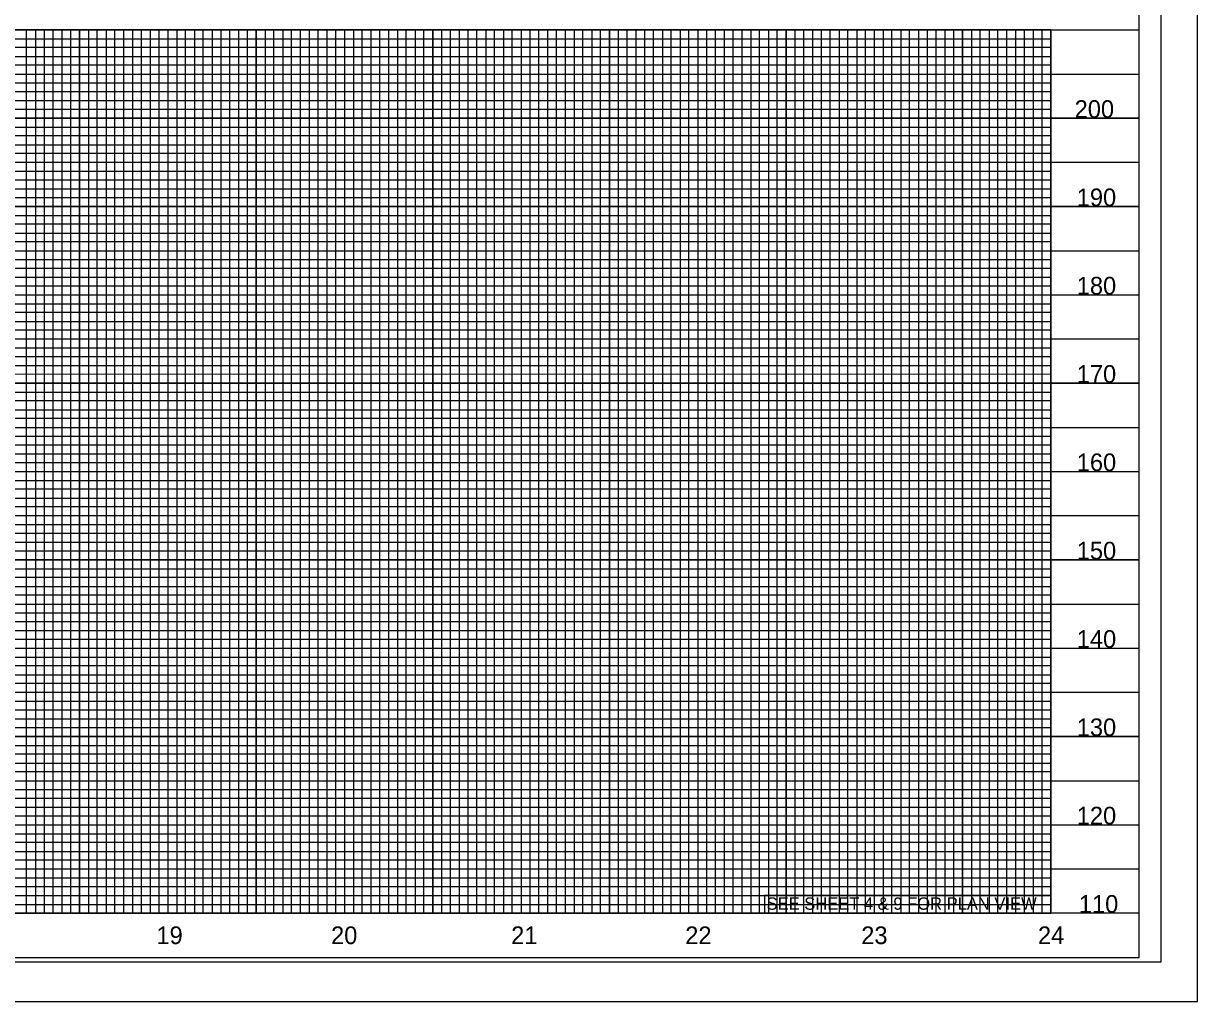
# Model space of a CAD drawing. Extents: x 1779926 to 1781626, y 618464 to 619564.
# Drawn here: x 1780961 to 1781626, y 618464 to 619018 of the extents above; entities that cross this region are included whole.
import ezdxf

# ---------------------------------------------------------------- set-up
doc = ezdxf.new("R2010")
doc.units = 0
for name, color, linetype in [('Exist Vertical Profile Horizontal Axis Label Major', 7, 'Continuous'), ('Exist Vertical Profile Vertical Axis Label', 7, 'Continuous'), ('Prop DSN Text', 7, 'Continuous'), ('Prop Grid Mask', 7, 'Continuous'), ('Sheet DOT Grid CELL', 7, 'Continuous'), ('Sheet Layout Profile Border Port 2', 7, 'Continuous'), ('Sheet Plot Border Inside CELL', 7, 'Continuous'), ('Sheet Plot Border Outside CELL', 7, 'Continuous'), ('Sheet Profile CELL', 7, 'Continuous'), ('Sheet Profile Grid Major CELL', 7, 'Continuous'), ('Sheet Profile Grid Middle CELL', 7, 'Continuous'), ('Sheet Profile Grid Minor CELL', 7, 'Continuous')]:
    doc.layers.add(name, color=color, linetype=linetype)

msp = doc.modelspace()

# ---------------------------------------------------------------- linework, layer by layer
at = {"layer": 'Prop Grid Mask'}
msp.add_lwpolyline([(1781542.96, 618524.19), (1781380.71, 618524.19), (1781380.71, 618514.19), (1781542.96, 618514.19)], close=True, dxfattribs=at)
at = {"layer": 'Sheet DOT Grid CELL'}
for p, q in [((1780092.96, 619014.19), (1781592.85, 619014.19)), ((1780992.96, 619014.19), (1780992.96, 618514.19)), ((1781042.96, 619014.19), (1781042.96, 618514.19)), ((1781092.96, 619014.19), (1781092.96, 618514.19)), ((1781142.96, 619014.19), (1781142.96, 618514.19)), ((1781192.96, 619014.19), (1781192.96, 618514.19)), ((1781242.96, 619014.19), (1781242.96, 618514.19)), ((1781292.96, 619014.19), (1781292.96, 618514.19)), ((1781342.96, 619014.19), (1781342.96, 618514.19)), ((1781392.96, 619014.19), (1781392.96, 618514.19)), ((1781442.96, 619014.19), (1781442.96, 618514.19)), ((1781492.96, 619014.19), (1781492.96, 618514.19)), ((1781542.96, 619014.19), (1781542.96, 618514.19)), ((1780092.96, 618964.19), (1781592.85, 618964.19)), ((1780092.96, 618914.19), (1781592.85, 618914.19)), ((1780092.96, 618864.19), (1781592.85, 618864.19)), ((1780092.96, 618814.19), (1781592.85, 618814.19)), ((1780092.96, 618764.19), (1781592.85, 618764.19)), ((1780092.96, 618714.19), (1781592.85, 618714.19)), ((1780092.96, 618664.19), (1781592.85, 618664.19)), ((1780092.96, 618614.19), (1781592.85, 618614.19)), ((1780092.96, 618564.19), (1781592.85, 618564.19))]:
    msp.add_line(p, q, dxfattribs=at)
at = {"layer": 'Sheet Layout Profile Border Port 2'}
msp.add_line((1781542.96, 619014.19), (1781442.96, 619014.19), dxfattribs=at)
msp.add_lwpolyline([(1780142.96, 619014.19), (1781542.96, 619014.19), (1781542.96, 618514.19), (1780142.96, 618514.19)], close=True, dxfattribs=at)
msp.add_lwpolyline([(1781442.96, 619014.19), (1780142.96, 619014.19), (1780142.96, 618514.19), (1781542.96, 618514.19), (1781542.96, 619014.19)], dxfattribs=at)
at = {"layer": 'Sheet Plot Border Inside CELL'}
msp.add_lwpolyline([(1779938.96, 618486.64), (1781605.46, 618486.64), (1781605.46, 619541.74), (1779938.96, 619541.74)], close=True, dxfattribs=at)
at = {"layer": 'Sheet Plot Border Outside CELL'}
msp.add_lwpolyline([(1779925.96, 618464.19), (1781625.96, 618464.19), (1781625.96, 619564.19), (1779925.96, 619564.19)], close=True, dxfattribs=at)
at = {"layer": 'Sheet Profile CELL'}
for p, q in [((1780092.96, 619014.19), (1781592.96, 619014.19)), ((1781592.96, 618514.19), (1780092.96, 618514.19)), ((1780092.96, 618489.19), (1781592.96, 618489.19))]:
    msp.add_line(p, q, dxfattribs=at)
msp.add_lwpolyline([(1781592.96, 619539.19), (1780092.96, 619539.19), (1780092.96, 618489.19), (1781592.96, 618489.19)], close=True, dxfattribs=at)
at = {"layer": 'Sheet Profile Grid Major CELL'}
for p, q in [((1780992.96, 619014.19), (1781042.96, 619014.19)), ((1781092.96, 619014.19), (1781142.96, 619014.19)), ((1781192.96, 619014.19), (1781242.96, 619014.19)), ((1781292.96, 619014.19), (1781342.96, 619014.19)), ((1781392.96, 619014.19), (1781442.96, 619014.19)), ((1781492.96, 619014.19), (1781542.96, 619014.19)), ((1781492.96, 618514.19), (1781492.96, 618514.19))]:
    msp.add_line(p, q, dxfattribs=at)
for points in [[(1780942.96, 618514.19), (1780992.96, 618514.19), (1780992.96, 619014.19), (1781042.96, 619014.19), (1781042.96, 618514.19), (1781092.96, 618514.19), (1781092.96, 619014.19), (1781142.96, 619014.19), (1781142.96, 618514.19), (1781192.96, 618514.19), (1781192.96, 619014.19), (1781242.96, 619014.19), (1781242.96, 618514.19), (1781292.96, 618514.19), (1781292.96, 619014.19), (1781342.96, 619014.19), (1781342.96, 618514.19), (1781392.96, 618514.19), (1781392.96, 619014.19), (1781442.96, 619014.19), (1781442.96, 618514.19), (1781492.96, 618514.19), (1781492.96, 618514.19), (1781492.96, 619014.19), (1781542.96, 619014.19), (1781542.96, 618514.19)], [(1781592.96, 618964.19), (1780092.96, 618964.19)], [(1781592.96, 618914.19), (1780092.96, 618914.19), (1780092.96, 618864.19), (1781592.96, 618864.19)], [(1781592.96, 618814.19), (1780092.96, 618814.19), (1780092.96, 618764.19), (1781592.96, 618764.19)], [(1781592.96, 618714.19), (1780092.96, 618714.19), (1780092.96, 618664.19), (1781592.96, 618664.19)], [(1781592.96, 618614.19), (1780092.96, 618614.19), (1780092.96, 618614.19), (1780092.96, 618564.19), (1781592.96, 618564.19)], [(1781592.96, 618514.19), (1780092.96, 618514.19)]]:
    msp.add_lwpolyline(points, dxfattribs=at)
at = {"layer": 'Sheet Profile Grid Middle CELL'}
for points in [[(1780917.96, 619014.19), (1780967.96, 619014.19), (1780967.96, 618514.19), (1781017.96, 618514.19), (1781017.96, 619014.19), (1781067.96, 619014.19), (1781067.96, 618514.19), (1781117.96, 618514.19), (1781117.96, 619014.19), (1781167.96, 619014.19), (1781167.96, 618514.19), (1781217.96, 618514.19), (1781217.96, 619014.19), (1781267.96, 619014.19), (1781267.96, 618514.19), (1781317.96, 618514.19), (1781317.96, 619014.19), (1781367.96, 619014.19), (1781367.96, 618514.19), (1781417.96, 618514.19), (1781417.96, 619014.19), (1781467.96, 619014.19), (1781467.96, 618514.19), (1781517.96, 618514.19), (1781517.96, 619014.19)], [(1780092.96, 618989.19), (1781592.96, 618989.19)], [(1781592.96, 618939.19), (1780092.96, 618939.19), (1780092.96, 618889.19), (1781592.96, 618889.19)], [(1781592.96, 618839.19), (1780092.96, 618839.19), (1780092.96, 618789.19), (1781592.96, 618789.19)], [(1781592.96, 618739.19), (1780092.96, 618739.19), (1780092.96, 618689.19), (1781592.96, 618689.19)], [(1781592.96, 618639.19), (1780092.96, 618639.19), (1780092.96, 618589.19), (1781592.96, 618589.19)], [(1781592.96, 618539.19), (1780092.96, 618539.19)]]:
    msp.add_lwpolyline(points, dxfattribs=at)
at = {"layer": 'Sheet Profile Grid Minor CELL'}
for p, q in [((1780142.96, 619009.19), (1781542.96, 619009.19)), ((1781542.96, 619004.19), (1780142.96, 619004.19)), ((1780142.96, 618999.19), (1781542.96, 618999.19)), ((1781542.96, 618994.19), (1780142.96, 618994.19)), ((1780142.96, 618984.19), (1781542.96, 618984.19)), ((1781542.96, 618979.19), (1780142.96, 618979.19)), ((1780142.96, 618974.19), (1781542.96, 618974.19)), ((1781542.96, 618969.19), (1780142.96, 618969.19)), ((1780142.96, 618959.19), (1781542.96, 618959.19)), ((1781542.96, 618954.19), (1780142.96, 618954.19)), ((1780142.96, 618949.19), (1781542.96, 618949.19)), ((1781542.96, 618944.19), (1780142.96, 618944.19)), ((1780142.96, 618934.19), (1781542.96, 618934.19)), ((1781542.96, 618929.19), (1780142.96, 618929.19)), ((1780142.96, 618924.19), (1781542.96, 618924.19)), ((1781542.96, 618919.19), (1780142.96, 618919.19)), ((1780142.96, 618909.19), (1781542.96, 618909.19)), ((1781542.96, 618904.19), (1780142.96, 618904.19)), ((1780142.96, 618899.19), (1781542.96, 618899.19)), ((1781542.96, 618894.19), (1780142.96, 618894.19)), ((1780142.96, 618884.19), (1781542.96, 618884.19)), ((1781542.96, 618879.19), (1780142.96, 618879.19)), ((1780142.96, 618874.19), (1781542.96, 618874.19)), ((1781542.96, 618869.19), (1780142.96, 618869.19)), ((1780142.96, 618859.19), (1781542.96, 618859.19)), ((1781542.96, 618854.19), (1780142.96, 618854.19)), ((1780142.96, 618849.19), (1781542.96, 618849.19)), ((1781542.96, 618844.19), (1780142.96, 618844.19)), ((1780142.96, 618834.19), (1781542.96, 618834.19)), ((1781542.96, 618829.19), (1780142.96, 618829.19)), ((1780142.96, 618824.19), (1781542.96, 618824.19)), ((1781542.96, 618819.19), (1780142.96, 618819.34)), ((1780142.96, 618809.19), (1781542.96, 618809.19)), ((1781542.96, 618804.19), (1780142.96, 618804.19)), ((1780142.96, 618799.19), (1781542.96, 618799.19)), ((1781542.96, 618794.19), (1780142.96, 618794.19)), ((1780142.96, 618784.19), (1781542.96, 618784.19)), ((1781542.96, 618779.19), (1780142.96, 618779.19)), ((1780142.96, 618774.19), (1781542.96, 618774.19)), ((1781542.96, 618769.19), (1780142.96, 618769.19)), ((1780142.96, 618759.19), (1781542.96, 618759.19)), ((1781542.96, 618754.19), (1780142.96, 618754.19)), ((1780142.96, 618749.19), (1781542.96, 618749.19)), ((1781542.96, 618744.19), (1780142.96, 618744.19)), ((1780142.96, 618734.19), (1781542.96, 618734.19)), ((1781542.96, 618729.19), (1780142.96, 618729.19)), ((1780142.96, 618724.19), (1781542.96, 618724.19)), ((1781542.96, 618719.19), (1780142.96, 618719.19)), ((1780142.96, 618709.19), (1781542.96, 618709.19)), ((1781542.96, 618704.19), (1780142.96, 618704.19)), ((1780142.96, 618699.19), (1781542.96, 618699.19)), ((1781542.96, 618694.19), (1780142.96, 618694.19)), ((1780142.96, 618684.19), (1781542.96, 618684.19)), ((1781542.96, 618679.19), (1780142.96, 618679.19)), ((1780142.96, 618674.19), (1781542.96, 618674.19)), ((1781542.96, 618669.19), (1780142.96, 618669.19)), ((1780142.96, 618659.19), (1781542.96, 618659.19)), ((1781542.96, 618654.19), (1780142.96, 618654.19)), ((1780142.96, 618649.19), (1781542.96, 618649.19)), ((1781542.96, 618644.19), (1780142.96, 618644.19)), ((1780142.96, 618634.19), (1781542.96, 618634.19)), ((1781542.96, 618629.19), (1780142.96, 618629.19)), ((1780142.96, 618624.19), (1781542.96, 618624.19)), ((1781542.96, 618619.19), (1780142.96, 618619.19)), ((1780142.96, 618609.19), (1781542.96, 618609.19)), ((1781542.96, 618604.19), (1780142.96, 618604.19)), ((1780142.96, 618599.19), (1781542.96, 618599.19)), ((1781542.96, 618594.19), (1780142.96, 618594.19)), ((1780142.96, 618584.19), (1781542.96, 618584.19)), ((1781542.96, 618579.19), (1780142.96, 618579.19)), ((1780142.96, 618574.19), (1781542.96, 618574.19)), ((1781542.96, 618569.19), (1780142.96, 618569.19)), ((1780142.96, 618559.19), (1781542.96, 618559.19)), ((1781542.96, 618554.19), (1780142.96, 618554.19)), ((1780142.96, 618549.19), (1781542.96, 618549.19)), ((1781542.96, 618544.19), (1780142.96, 618544.19)), ((1780142.96, 618534.19), (1781542.96, 618534.19)), ((1781542.96, 618529.19), (1780142.96, 618529.19)), ((1780142.96, 618524.19), (1781542.96, 618524.19)), ((1780142.96, 618519.19), (1781542.96, 618519.19)), ((1781542.96, 618519.19), (1781542.96, 618519.19))]:
    msp.add_line(p, q, dxfattribs=at)
for points in [[(1780957.96, 618514.19), (1780962.96, 618514.19), (1780962.96, 619014.19), (1780972.96, 619014.19), (1780972.96, 618514.19), (1780977.96, 618514.19)], [(1780977.96, 618514.19), (1780977.96, 619014.19), (1780982.96, 619014.19), (1780982.96, 618514.19), (1780987.96, 618514.19), (1780987.96, 619014.19), (1780997.96, 619014.19), (1780997.96, 618514.19), (1781002.96, 618514.19), (1781002.96, 619014.19), (1781007.96, 619014.19), (1781007.96, 618514.19), (1781012.96, 618514.19), (1781012.96, 619014.19), (1781022.96, 619014.19), (1781022.96, 618514.19), (1781027.96, 618514.19), (1781027.96, 619014.19), (1781032.96, 619014.19), (1781032.96, 618514.19), (1781037.96, 618514.19), (1781037.96, 619014.19), (1781047.96, 619014.19), (1781047.96, 618514.19), (1781052.96, 618514.19), (1781052.96, 619014.19), (1781057.96, 619014.19), (1781057.96, 618514.19), (1781062.96, 618514.19), (1781062.96, 619014.19), (1781072.96, 619014.19), (1781072.96, 618514.19), (1781077.96, 618514.19), (1781077.96, 619014.19), (1781082.96, 619014.19), (1781082.96, 618514.19), (1781087.96, 618514.19), (1781087.96, 619014.19), (1781097.96, 619014.19), (1781097.96, 618514.19), (1781102.96, 618514.19), (1781102.96, 619014.19), (1781107.96, 619014.19), (1781107.96, 618514.19), (1781112.96, 618514.19), (1781112.96, 619014.19), (1781122.96, 619014.19), (1781122.96, 618514.19), (1781127.96, 618514.19), (1781127.96, 619014.19), (1781132.96, 619014.19), (1781132.96, 618514.19), (1781137.96, 618514.19), (1781137.96, 619014.19), (1781147.96, 619014.19), (1781147.96, 618514.19), (1781152.96, 618514.19), (1781152.96, 619014.19), (1781157.96, 619014.19), (1781157.96, 618514.19), (1781162.96, 618514.19), (1781162.96, 619014.19), (1781172.96, 619014.19), (1781172.96, 618514.19), (1781177.96, 618514.19), (1781177.96, 619014.19), (1781182.96, 619014.19), (1781182.96, 618514.19), (1781187.96, 618514.19), (1781187.96, 619014.19), (1781197.96, 619014.19), (1781197.96, 618514.19), (1781202.96, 618514.19), (1781202.96, 619014.19), (1781207.96, 619014.19), (1781207.96, 618514.19), (1781212.96, 618514.19), (1781212.96, 619014.19), (1781222.96, 619014.19), (1781222.96, 618514.19), (1781227.96, 618514.19), (1781227.96, 619014.19), (1781232.96, 619014.19), (1781232.96, 618514.19), (1781237.96, 618514.19), (1781237.96, 619014.19), (1781247.96, 619014.19), (1781247.96, 618514.19), (1781252.96, 618514.19), (1781252.96, 619014.19), (1781257.96, 619014.19), (1781257.96, 618514.19), (1781262.96, 618514.19), (1781262.96, 619014.19), (1781272.96, 619014.19), (1781272.96, 618514.19), (1781277.96, 618514.19), (1781277.96, 619014.19), (1781282.96, 619014.19), (1781282.96, 618514.19)], [(1781282.96, 618514.19), (1781287.96, 618514.19), (1781287.96, 619014.19), (1781297.96, 619014.19), (1781297.96, 618514.19), (1781302.96, 618514.19), (1781302.96, 619014.19), (1781307.96, 619014.19), (1781307.96, 618514.19), (1781312.96, 618514.19), (1781312.96, 619014.19), (1781322.96, 619014.19), (1781322.96, 618514.19), (1781327.96, 618514.19), (1781327.96, 619014.19), (1781332.96, 619014.19), (1781332.96, 618514.19), (1781337.96, 618514.19), (1781337.96, 619014.19), (1781347.96, 619014.19), (1781347.96, 618514.19), (1781352.96, 618514.19), (1781352.96, 619014.19), (1781357.96, 619014.19), (1781357.96, 618514.19), (1781362.96, 618514.19), (1781362.96, 619014.19), (1781372.96, 619014.19), (1781372.96, 618514.19), (1781377.96, 618514.19), (1781377.96, 619014.19), (1781382.96, 619014.19), (1781382.96, 618514.19), (1781387.96, 618514.19), (1781387.96, 619014.19), (1781397.96, 619014.19), (1781397.96, 618514.19), (1781402.96, 618514.19), (1781402.96, 619014.19), (1781407.96, 619014.19), (1781407.96, 618514.19), (1781412.96, 618514.19), (1781412.96, 619014.19), (1781422.96, 619014.19), (1781422.96, 618514.19), (1781427.96, 618514.19), (1781427.96, 619014.19), (1781432.96, 619014.19), (1781432.96, 618514.19), (1781437.96, 618514.19), (1781437.96, 619014.19), (1781447.96, 619014.19), (1781447.96, 618514.19), (1781452.96, 618514.19), (1781452.96, 619014.19), (1781457.96, 619014.19), (1781457.96, 618514.19), (1781462.96, 618514.19), (1781462.96, 619014.19), (1781472.96, 619014.19), (1781472.96, 618514.19), (1781477.96, 618514.19), (1781477.96, 619014.19), (1781482.96, 619014.19), (1781482.96, 618514.19), (1781487.96, 618514.19), (1781487.96, 619014.19), (1781497.96, 619014.19), (1781497.96, 618514.19), (1781502.96, 618514.19), (1781502.96, 619014.19), (1781507.96, 619014.19), (1781507.96, 618514.19), (1781512.96, 618514.19), (1781512.96, 619014.19), (1781522.96, 619014.19), (1781522.96, 618514.19), (1781527.96, 618514.19), (1781527.96, 619014.19), (1781532.96, 619014.19), (1781532.96, 618514.19), (1781537.96, 618514.19), (1781537.96, 619014.19), (1781542.96, 619014.19)]]:
    msp.add_lwpolyline(points, dxfattribs=at)

# ---------------------------------------------------------------- texts
at = {"layer": 'Exist Vertical Profile Horizontal Axis Label Major'}
for s, p in [('19', (1781036.47, 618496.69)), ('20', (1781135.35, 618496.69)), ('21', (1781237.33, 618496.69)), ('22', (1781335.89, 618496.69)), ('23', (1781435.57, 618496.69)), ('24', (1781535.63, 618496.69))]:
    msp.add_text(s, height=10, dxfattribs=at).set_placement(p)
at = {"layer": 'Exist Vertical Profile Vertical Axis Label'}
for s, p in [('200', (1781556.39, 618964.44)), ('190', (1781557.59, 618914.44)), ('180', (1781557.59, 618864.44)), ('170', (1781557.59, 618814.44)), ('160', (1781557.59, 618764.44)), ('150', (1781557.59, 618714.44)), ('140', (1781557.59, 618664.44)), ('130', (1781557.59, 618614.44)), ('120', (1781557.59, 618564.44)), ('110', (1781558.79, 618514.44))]:
    msp.add_text(s, height=10, dxfattribs=at).set_placement(p)
at = {"layer": 'Prop DSN Text'}
msp.add_text('SEE SHEET 4 & 9 FOR PLAN VIEW', height=7, dxfattribs=at).set_placement((1781381.95, 618516.14))

doc.saveas('drawing.dxf')
